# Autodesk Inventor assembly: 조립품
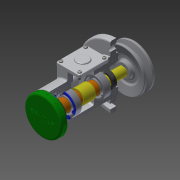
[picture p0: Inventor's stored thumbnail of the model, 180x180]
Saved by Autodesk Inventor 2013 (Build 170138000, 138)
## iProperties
Created: 2017-05
Part Number: 조립품
Document SubType Name: Assembly
Designer: MR
Author: MR
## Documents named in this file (19)
- C:\Users\MR\Desktop\470508V1001\조립품.iam
- C:\Users\MR\Desktop\470508V1001\본체.ipt
- C:\Users\MR\Desktop\470508V1001\축.ipt
- C:\Users\MR\Desktop\470508V1001\부시1.ipt
- C:\Users\MR\Desktop\470508V1001\키 4 x 4 x 18.ipt
- C:\Users\MR\Desktop\470508V1001\V-벨트풀리.ipt
- C:\Users\MR\Desktop\470508V1001\와셔 4x16.ipt
- C:\Users\MR\Desktop\470508V1001\볼트 M4 x 10.ipt
- C:\Users\MR\Desktop\470508V1001\베어링 15 x 35 x 11.ipt
- C:\Users\MR\Desktop\470508V1001\멈춤링 35x1.6.ipt
- C:\Users\MR\Desktop\470508V1001\멈춤링 15 x 1.ipt
- C:\Users\MR\Desktop\470508V1001\부시2.ipt
- C:\Users\MR\Desktop\470508V1001\와셔 10x21.ipt
- C:\Users\MR\Desktop\470508V1001\너트 M10.ipt
- C:\Users\MR\Desktop\470508V1001\사이드 커버.ipt
- 사이드 커버.ipt
- C:\Users\MR\Desktop\470508V1001\십자볼트 M3 x 10.ipt
- C:\Users\MR\Desktop\470508V1001\오일 실 15 25 7.ipt
- C:\Users\MR\Desktop\470508V1001\탑 커버.ipt
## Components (2 placed, 2 different names)
1. V-벨트풀리:1 — 각도:2
2. ISO 4017 M4 x 10:1
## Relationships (1: Angle 1)
- 각도:2 [Angle]: V-벨트풀리:1
